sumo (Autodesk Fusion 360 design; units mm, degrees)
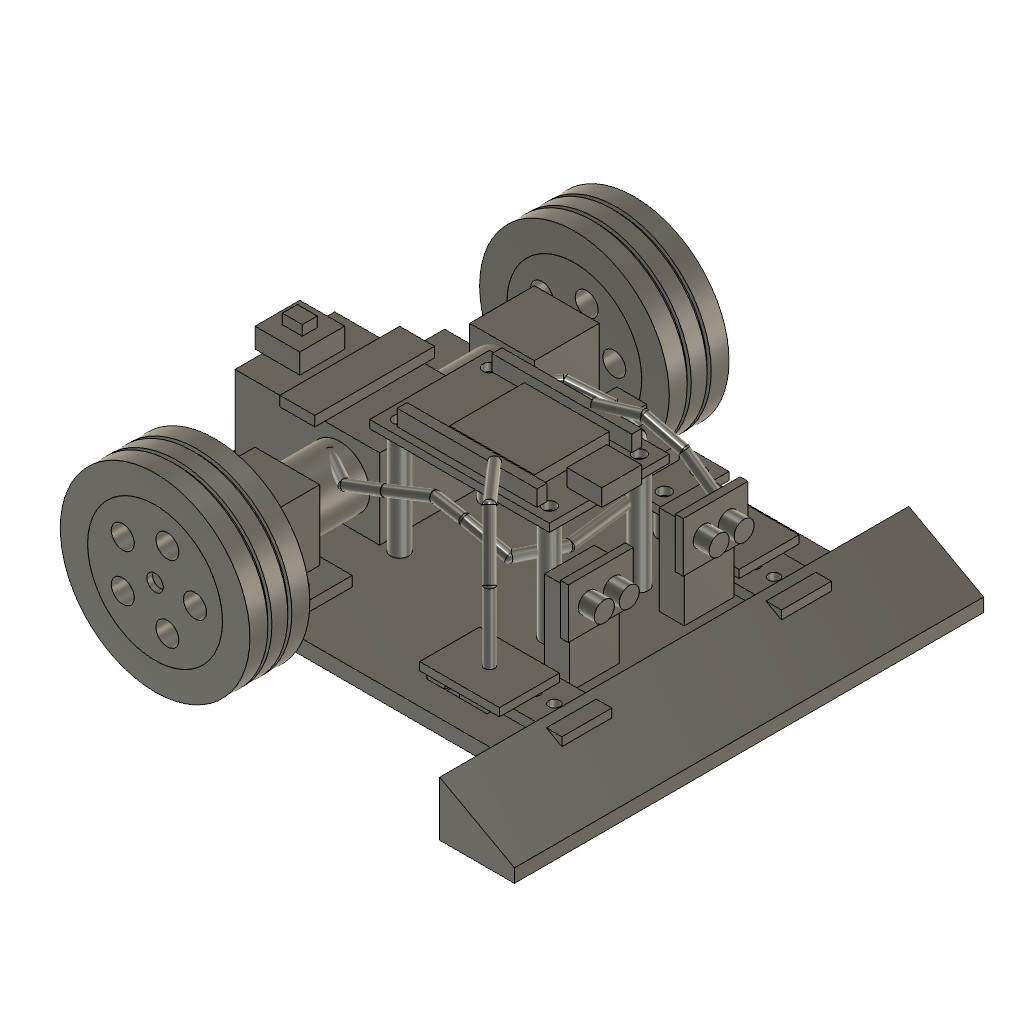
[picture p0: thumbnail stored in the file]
part number: 2026-11-25-00-38-47-800
part number: 2026-11-25-00-38-47-888
part number: 2026-11-25-00-38-47-910
part number: 2026-11-25-00-38-47-929
part number: 2026-11-25-00-38-47-952
part number: 2026-11-25-00-38-47-974
part number: 2026-11-25-00-38-48-000
part number: 2026-11-25-00-38-48-021
part number: 2026-11-25-00-38-48-041
part number: 2026-11-25-00-38-48-063
part number: 2026-11-25-00-38-48-090
part number: 2026-11-25-00-38-48-115
part number: 2026-11-25-00-38-48-140
part number: 2026-11-25-00-38-48-175
base_feature "Base Feature1" bodies "Chassis plate"
ground "Pin"
base_feature "Base Feature1" bodies "Motor saddle", "Motor can envelope", "Gearbox envelope", "Output shaft"
base_feature "Base Feature1" bodies "38 mm traction tire", "Wheel hub"
as_built_joint "As-built1"
sketch "Left wheel rotation pivot reference" plane through (0, 0, 0) normal (0, 0, 1) x axis (1, 0, 0)
as_built_joint "As-built2"
base_feature "Base Feature1" bodies "Motor saddle", "Motor can envelope", "Gearbox envelope", "Output shaft"
base_feature "Base Feature1" bodies "38 mm traction tire", "Wheel hub"
as_built_joint "As-built3"
sketch "Right wheel rotation pivot reference" plane through (0, 0, 0) normal (0, 0, 1) x axis (1, 0, 0)
as_built_joint "As-built4"
base_feature "Base Feature1" bodies "Skid mount", "Rounded ground contact"
base_feature "Base Feature1" bodies "Full width wedge with blunt front edge and mounting tabs"
base_feature "Base Feature1" bodies "Battery pack envelope", "Retaining strap over pack", "Slide switch housing", "Slide switch actuator"
base_feature "Base Feature1" bodies "PCB envelope", "Controller RF shield", "Accessible USB socket", "Left header", "Right header", "PCB standoff", "PCB standoff (1)", "PCB standoff (2)"
base_feature "Base Feature1" bodies "Driver PCB envelope", "Driver IC", "Screw terminal", "Driver board standoff", "Driver board standoff (1)", "Driver board standoff (2)", "Driver board standoff (3)"
base_feature "Base Feature1" bodies "Left edge sensor PCB", "Left downward reflectance optics", "Left edge sensor spacer", "Right edge sensor PCB", "Right downward reflectance optics", "Right edge sensor spacer"
base_feature "Base Feature1" bodies "Left front sensor mount", "Left front IR sensor board", "Left emitter", "Left receiver", "Right front sensor mount", "Right front IR sensor board", "Right emitter", "Right receiver"
base_feature "Base Feature1" bodies "Battery power lead", "Left motor lead", "Right motor lead", "Front sensor harness", "Edge sensor harness"
as_built_joint "As-built5"
as_built_joint "As-built6"
as_built_joint "As-built7"
as_built_joint "As-built8"
as_built_joint "As-built9"
as_built_joint "As-built10"
as_built_joint "As-built11"
as_built_joint "As-built12"
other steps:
create_component "CreateComponent1"
create_component "CreateComponent2"
create_component "CreateComponent3"
create_component "CreateComponent4"
create_component "CreateComponent5"
create_component "CreateComponent6"
create_component "CreateComponent7"
create_component "CreateComponent8"
create_component "CreateComponent9"
create_component "CreateComponent10"
create_component "CreateComponent11"
create_component "CreateComponent12"
create_component "CreateComponent13"
named bodies: "Chassis plate", "Motor saddle", "Motor can envelope", "Gearbox envelope", "Output shaft", "38 mm traction tire", "Wheel hub", "Skid mount", "Rounded ground contact", "Full width wedge with blunt front edge and mounting tabs", "Battery pack envelope", "Retaining strap over pack", "Slide switch housing", "Slide switch actuator", "PCB envelope", "Controller RF shield", "Accessible USB socket", "Left header", "Right header", "PCB standoff", "PCB standoff (1)", "PCB standoff (2)", "PCB standoff (3)", "Driver PCB envelope", "Driver IC", "Screw terminal", "Driver board standoff", "Driver board standoff (1)", "Driver board standoff (2)", "Driver board standoff (3)", "Left edge sensor PCB", "Left downward reflectance optics", "Left edge sensor spacer", "Right edge sensor PCB", "Right downward reflectance optics", "Right edge sensor spacer", "Left front sensor mount", "Left front IR sensor board", "Left emitter", "Left receiver", "Right front sensor mount", "Right front IR sensor board", "Right emitter", "Right receiver", "Battery power lead", "Left motor lead", "Right motor lead", "Front sensor harness", "Edge sensor harness"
